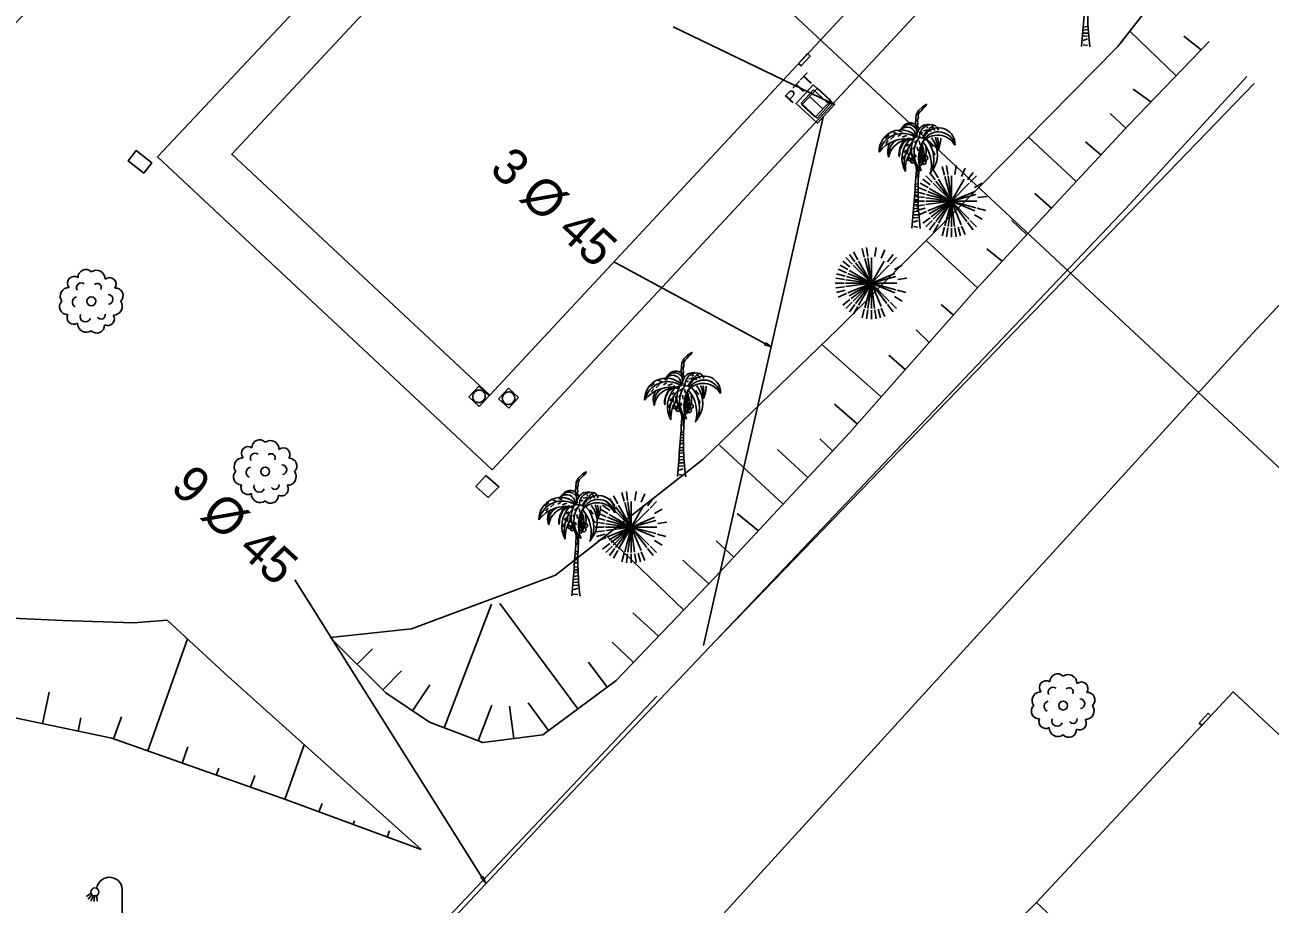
# Model space of a CAD drawing. Extents: x 343997 to 344255, y 298512 to 298767.
# Drawn here: x 344085.39 to 344119.67, y 298730.51 to 298754.72 of the extents above; entities that cross this region are included whole.
import ezdxf

# ---------------------------------------------------------------- set-up
doc = ezdxf.new("R2010")
doc.units = 0
for name, color, linetype in [('Default', 7, 'Continuous'), ('DH_CADRE -CARTOUCHE', 7, 'Continuous'), ('DH_CADRE-CARTOUCHE', 7, 'Continuous'), ('DH_NORD', 7, 'Continuous'), ('DIR-Projet VRD1', 7, 'Continuous'), ('EL-coffret', 7, 'Continuous'), ('GO_DALLE', 7, 'Continuous'), ('O-Projet New VRD', 7, 'Continuous'), ('PC_REBAR', 7, 'Continuous'), ('PS_OBJECT', 7, 'Continuous'), ('PS_PLATE', 7, 'Continuous'), ('RES_EAU PLUVIALE', 7, 'Continuous'), ('RES_ELECTRICITE', 7, 'Continuous')]:
    doc.layers.add(name, color=color, linetype=linetype)

# ---------------------------------------------------------------- blocks, each defined once
blk = doc.blocks.new('CT2')
at = {"layer": 'Default'}
blk.add_lwpolyline([(0, 0), (0.1, 0), (0.1, 0.1), (0, 0.1)], close=True, dxfattribs=at)
blk.add_lwpolyline([(0.05, 0.1), (0.05, 0)], dxfattribs=at)
blk.add_text('PTT', height=0.06, dxfattribs=at).set_placement((-0.03, 0.1425))
blk = doc.blocks.new('REG_INC')
at = {"layer": 'Default'}
for p, q in [((0, 0.1), (0.1, 0.1)), ((0, 0), (0, 0.1)), ((0.1, 0.1), (0.1, 0)), ((0.1, 0), (0, 0))]:
    blk.add_line(p, q, dxfattribs=at)
for centre, start, end in [((0.05, 0.0498), 90.00577, 135.00577), ((0.05, 0.05), 45.00687, 90.00687), ((0.0498, 0.05), 135.00554, 180.00554), ((0.0501, 0.05), 180.00663, 225.00663), ((0.0499, 0.0498), 225.00686, 270.00686), ((0.0499, 0.05), 270.00577, 315.00577), ((0.0499, 0.0499), 0.00663, 45.00663), ((0.0501, 0.0499), 315.00554, 0.00554)]:
    blk.add_arc(centre, 0.044, start, end, dxfattribs=at)
blk = doc.blocks.new('EDF1')
at = {"layer": 'Default'}
for points in [[(-0.0855, 0.1462), (-0.0985, 0.1373)], [(-0.083, 0.1422), (-0.0931, 0.1303)], [(-0.0793, 0.1397), (-0.086, 0.1257)], [(-0.0753, 0.1388), (-0.0781, 0.1235)], [(-0.0701, 0.14), (-0.0684, 0.1241)], [(0, 0.01), (0, 0.15)]]:
    blk.add_lwpolyline(points, dxfattribs=at)
for centre, radius in [((-0.075, 0.15), 0.0112), ((0, 0), 0.01)]:
    blk.add_circle(centre, radius, dxfattribs=at)
blk.add_arc((-0.035, 0.155), 0.0354, 351.8699, 171.8699, dxfattribs=at)
blk = doc.blocks.new('COCO')
at = {"layer": 'Default'}
for p, q in [((-0.0037, 0.106), (0.0056, 0.1071)), ((0.0058, 0.114), (-0.003, 0.1162)), ((-0.0026, 0.1226), (0.0061, 0.1212)), ((-0.0046, 0.0891), (0.0052, 0.0927)), ((0.0054, 0.0998), (-0.0041, 0.0985)), ((-0.0068, 0.0371), (0.0045, 0.0374)), ((0.0045, 0.047), (-0.0065, 0.0453)), ((-0.0062, 0.0537), (0.0046, 0.0552)), ((0.0047, 0.0655), (-0.0058, 0.0642)), ((0.0046, 0.0033), (-0.0076, 0.0051)), ((-0.0073, 0.017), (0.0045, 0.0209)), ((0.0045, 0.0292), (-0.007, 0.0288))]:
    blk.add_line(p, q, dxfattribs=at)
for points in [[(0.0029, 0.2551), (-0.0016, 0.2896), (0.0002, 0.3125), (0.0059, 0.3241), (0.0173, 0.3348), (0.0189, 0.3356), (0.0282, 0.3415), (0.0266, 0.3373), (0.02, 0.3318), (0.0143, 0.3247), (0.0093, 0.32), (0.0081, 0.3165), (0.0057, 0.3133), (0.0057, 0.3099), (0.006, 0.3037), (0.0039, 0.2989), (0.0039, 0.2944), (0.0049, 0.2877), (0.0037, 0.2841), (0.0013, 0.2736)], [(0.0013, 0.2736), (0.0036, 0.2813), (0.0046, 0.2746)], [(0.0283, 0.2765), (0.0331, 0.2786)], [(-0.0746, 0.2559), (-0.0864, 0.2483)], [(-0.077, 0.2413), (-0.0836, 0.2333)], [(-0.0607, 0.2534), (-0.0704, 0.2443)], [(-0.0636, 0.2639), (-0.0541, 0.2608)], [(-0.0421, 0.258), (-0.0503, 0.2523)], [(-0.0487, 0.268), (-0.0386, 0.265)], [(-0.0183, 0.2493), (-0.0348, 0.2417), (-0.0401, 0.2307), (-0.0448, 0.2203), (-0.0471, 0.2086), (-0.0474, 0.2023), (-0.0466, 0.1973), (-0.0455, 0.2054), (-0.0451, 0.2146), (-0.0387, 0.2292), (-0.0351, 0.2354), (-0.0284, 0.2404), (-0.0233, 0.2445), (-0.0012, 0.2495)], [(-0.0256, 0.2553), (-0.0385, 0.2508)], [(0.0015, 0.2414), (-0.0056, 0.2352)], [(0.0081, 0.2404), (0.0106, 0.2299)], [(0.0133, 0.2608), (0.0185, 0.2634)], [(0.0196, 0.2687), (0.0323, 0.2715)], [(-0.0276, 0.2151), (-0.0329, 0.2086)], [(-0.0203, 0.2314), (-0.0274, 0.2258)], [(-0.023, 0.2152), (-0.0237, 0.2043)], [(-0.0161, 0.2218), (-0.0158, 0.2122)], [(-0.004, 0.2247), (-0.0081, 0.2179)], [(0.0022, 0.224), (0.0043, 0.213)], [(0.0385, 0.237), (0.0469, 0.2254)], [(0.0473, 0.2115), (0.0509, 0.2012)], [(-0.0321, 0.1997), (-0.0364, 0.19)], [(-0.0059, 0.2024), (-0.0083, 0.1998)], [(-0.0025, 0.2032), (0.0002, 0.1954)], [(-0.0055, 0.0716), (0.0048, 0.0717), (0.0049, 0.0787), (-0.0051, 0.0795)]]:
    blk.add_lwpolyline(points, dxfattribs=at)
for centre, radius in [((-0.0187, 0.1897), 0.00384), ((-0.0144, 0.1978), 0.00616), ((-0.0124, 0.1896), 0.00376), ((-0.011, 0.184), 0.00471), ((0.0134, 0.1862), 0.00549), ((0.0208, 0.1822), 0.00626), ((0.0254, 0.1938), 0.00628)]:
    blk.add_circle(centre, radius, dxfattribs=at)
for centre, radius, start, end in [((-0.0123, 0.259), 0.0323, 122.3475, 158.7636), ((-0.0199, 0.2618), 0.0238, 4.5218, 154.101), ((-0.0252, 0.2556), 0.0231, 4.2441, 134.2103), ((-0.016, 0.2647), 0.0255, 21.0861, 122.3475), ((0.0376, 0.2508), 0.0372, 113.7681, 175.3309), ((0.0376, 0.2508), 0.0372, 113.7681, 175.3309), ((0.0418, 0.2527), 0.0326, 97.1248, 183.9512), ((0.1025, 0.2053), 0.0958, 126.6858, 153.1664), ((0.0618, 0.2316), 0.0451, 356.1627, 159.0009), ((0.0344, 0.2407), 0.0451, 69.0817, 104.862), ((-0.0254, 0.228), 0.0869, 28.4725, 37.0965), ((0.0493, 0.2767), 0.00679, 35.3205, 126.6858), ((-0.0054, 0.2379), 0.0738, 25.8194, 35.3205), ((-0.0427, 0.2113), 0.0595, 43.6121, 181.4625), ((-0.0291, 0.1543), 0.0918, 76.7389, 142.8025), ((-0.038, 0.1964), 0.0648, 57.9192, 166.6201), ((-0.0196, 0.1874), 0.0565, 78.514, 171.3504), ((-0.032, 0.2055), 0.0433, 119.0834, 188.7621), ((0.0362, 0.1922), 0.0754, 136.7113, 208.8221), ((0.062, 0.2159), 0.0753, 153.0868, 230.1124), ((0.0659, 0.2068), 0.0718, 142.3554, 222.2794), ((-0.0007, 0.2465), 0.00563, 81.7475, 144.3035), ((-0.0189, 0.121), 0.1324, 71.3715, 81.7475), ((0.0294, 0.2595), 0.0256, 198.6765, 199.7627), ((0.0963, 0.1939), 0.09, 143.9866, 203.4288), ((0.059, 0.2015), 0.0548, 29.5654, 139.3517), ((-0.0341, 0.19), 0.0828, 46.9767, 50.1231), ((0.0609, 0.2187), 0.0468, 12.1077, 148.3146), ((-0.0157, 0.2027), 0.074, 51.2475, 54.5217), ((-0.0341, 0.19), 0.0828, 334.0687, 41.194), ((-0.1005, 0.1577), 0.1786, 37.5668, 40.5156), ((-0.0157, 0.2027), 0.074, 315.1472, 39.0239), ((-0.1704, 0.1849), 0.2327, 7.5978, 16.3666), ((-0.0254, 0.228), 0.0869, 350.8883, 14.7063), ((-0.0482, 0.2552), 0.1161, 339.3597, 356.5925), ((-0.03, 0.212), 0.0482, 151.1331, 199.5942), ((0.0551, 0.179), 0.0879, 137.733, 194.3716), ((0.0649, 0.1599), 0.0949, 145.5146, 182.4528), ((0.0544, 0.1816), 0.0474, 137.1953, 172.8987), ((0.0308, 0.2014), 0.0226, 121.4297, 182.29), ((2.7302, 0.0106), 2.7266, 175.4791, 176.5597), ((0.0311, 0.2152), 0.0219, 141.856, 191.5175), ((0.0242, 0.1964), 0.0147, 110.9727, 165.9756), ((0.0404, 0.1878), 0.0354, 125.0585, 146.3893), ((0.0398, 0.2098), 0.0301, 136.4569, 162.0685), ((0.0357, 0.2084), 0.0244, 133.1184, 172.7534), ((-0.0759, 0.1958), 0.0922, 344.8505, 15.8988), ((-0.0404, 0.2045), 0.0619, 329.4666, 26.6793), ((-0.0289, 0.211), 0.0564, 317.8279, 12.3386), ((-0.0543, 0.1744), 0.096, 344.8781, 41.1461), ((-8.5428, 0.7294), 8.5622, 355.11326, 356.26352), ((-0.0279, 0.1637), 0.0281, 2.1499, 36.6325), ((0.0372, 0.1847), 0.0277, 133.5956, 173.487), ((0.0808, 0.1542), 0.0777, 142.2358, 156.28), ((-0.0265, 0.1505), 0.0316, 339.9997, 25.7228), ((0.0199, 0.166), 0.0176, 166.9443, 185.5966)]:
    blk.add_arc(centre, radius, start, end, dxfattribs=at)
blk.add_ellipse((2.7425, 0.0272), major_axis=(-2.7371, 0.0966), ratio=0.529859, start_param=6.255729, end_param=6.369141, dxfattribs=at)
blk = doc.blocks.new('ARB1')
at = {"layer": 'Default'}
blk.add_circle((0, 0), 0.0122, dxfattribs=at)
for centre, radius, start, end in [((-0.0471, 0.0503), 0.0183, 53.9554, 222.2066), ((-0.0153, 0.0664), 0.0211, 43.6925, 183.5969), ((0.0139, 0.0613), 0.0241, 358.4583, 125.1928), ((-0.0613, 0.0139), 0.0241, 88.4583, 215.1928), ((-0.0276, 0.037), 0.0134, 52.4396, 209.5496), ((0.0164, 0.038), 0.0112, 330.5895, 133.7127), ((0.0501, 0.0468), 0.0183, 325.1444, 131.0175), ((0.0664, 0.0153), 0.0211, 313.6925, 93.5969), ((-0.0373, -0.0024), 0.0149, 103.7092, 242.3465), ((0.0458, 0.0052), 0.0137, 276.6214, 88.967), ((0.0613, -0.0139), 0.0241, 268.4583, 35.1928), ((-0.0664, -0.0153), 0.0211, 133.6925, 273.5969), ((-0.0478, -0.0443), 0.019, 155.2243, 300.9377), ((-0.0139, -0.0613), 0.0241, 178.4583, 305.1928), ((-0.0163, -0.042), 0.0148, 159.5371, 338.1663), ((0.0153, -0.0664), 0.0211, 223.6925, 3.5969), ((0.0271, -0.038), 0.0112, 210.5895, 13.7127), ((0.0448, -0.0483), 0.0188, 243.1323, 33.0297)]:
    blk.add_arc(centre, radius, start, end, dxfattribs=at)
blk = doc.blocks.new('ARB2')
at = {"layer": 'Default'}
for p, q in [((-0.0513, 0.0525), (-0.0688, 0.0702)), ((-0.0438, 0.0589), (-0.0588, 0.0786)), ((-0.0356, 0.0642), (-0.0481, 0.0858)), ((-0.0181, 0.0716), (-0.0244, 0.0956)), ((-0.0088, 0.0736), (-0.0119, 0.0983)), ((0.0106, 0.0736), (0.0144, 0.0983)), ((0.0287, 0.0684), (0.0388, 0.0914)), ((0.0456, 0.0589), (0.0612, 0.0786)), ((0.0531, 0.0525), (0.0706, 0.0702)), ((-0.0675, 0.0286), (-0.09, 0.0381)), ((-0.0631, 0.0373), (-0.0844, 0.0497)), ((-0.0575, 0.0453), (-0.0775, 0.0605)), ((0.065, 0.0373), (0.0862, 0.0497)), ((-0.0731, 0), (-0.0981, 0)), ((-0.0725, 0.01), (-0.0969, 0.0133)), ((-0.0706, 0.0195), (-0.0944, 0.0259)), ((0.0744, 0.01), (0.0987, 0.0133)), ((-0.0725, -0.01), (-0.0969, -0.0133)), ((-0.0706, -0.0195), (-0.0944, -0.0259)), ((-0.0675, -0.0287), (-0.09, -0.0383)), ((0.0725, -0.0195), (0.0963, -0.0259)), ((-0.0575, -0.0455), (-0.0775, -0.0605)), ((-0.0513, -0.0527), (-0.0688, -0.0702)), ((-0.0438, -0.0591), (-0.0588, -0.0787)), ((-0.0356, -0.0644), (-0.0481, -0.0859)), ((0.0456, -0.0591), (0.0612, -0.0787)), ((0.0531, -0.0527), (0.0706, -0.0702)), ((0.065, -0.0373), (0.0862, -0.0498)), ((-0.0181, -0.0717), (-0.0244, -0.0956)), ((-0.0088, -0.0737), (-0.0119, -0.0983)), ((0.0013, -0.0741), (0.0013, -0.0989)), ((0.0106, -0.0737), (0.0144, -0.0983)), ((0.02, -0.0717), (0.0263, -0.0956)), ((0.0287, -0.0686), (0.0388, -0.0916))]:
    blk.add_line(p, q, dxfattribs=at)
for points in [[(0.0013, 0.0008), (0.0013, 0), (-0.0081, 0.0695)], [(0.0362, 0.0608), (0.0013, 0), (0.0013, 0.0702)], [(-0.0688, 0.0091), (0.0013, 0), (-0.0338, 0.0608)], [(-0.0487, 0.0495), (0.0013, 0), (-0.0669, 0.0181)], [(-0.0419, 0.0556), (0.0013, 0), (-0.0638, 0.0269)], [(-0.0169, 0.0677), (0.0013, 0), (-0.06, 0.035)], [(0.0656, 0.0269), (0.0013, 0), (0.0506, 0.0495)], [(-0.0487, -0.0497), (0.0013, 0), (-0.0694, 0)], [(-0.0638, -0.0269), (0.0013, 0), (-0.0688, -0.0092)], [(-0.0169, -0.0678), (0.0013, 0), (-0.06, -0.0352)], [(-0.0544, -0.0428), (0.0013, 0), (-0.0338, -0.0608)], [(-0.0081, -0.0695), (0.0013, 0), (-0.0419, -0.0558)], [(0.0013, -0.0702), (0.0013, 0), (0, 0)], [(0.0688, 0.0181), (0.0013, 0), (0.0713, 0)], [(0.0438, -0.0558), (0.0013, 0), (0.0656, -0.0269)], [(0.0506, -0.0497), (0.0013, 0), (0.0688, -0.0181)], [(0.01, -0.0695), (0.0013, 0), (0.0281, -0.0648)], [(0.0019, 0), (0.0013, 0), (0.0013, -0.0009)]]:
    blk.add_lwpolyline(points, dxfattribs=at)

msp = doc.modelspace()

# ---------------------------------------------------------------- linework, layer by layer
at = {"layer": 'DH_CADRE -CARTOUCHE'}
for points in [[(344112.242, 298759.628), (344105.157, 298766.24), (344091.09, 298751.159), (344098.189, 298744.522)], [(343997.309, 298660.673), (344147.183, 298520.807), (344245.09, 298625.72), (344095.215, 298765.586)]]:
    msp.add_lwpolyline(points, close=True, dxfattribs=at)
at = {"layer": 'DH_CADRE-CARTOUCHE'}
for points in [[(344035.538, 298697.865), (344038.262, 298695.856), (344041.267, 298693.813), (344044.479, 298691.842), (344047.664, 298690.365), (344050.648, 298689.339), (344052.822, 298689.099), (344054.599, 298689.128), (344056.124, 298689.428), (344057.609, 298690.129), (344058.956, 298690.85), (344060.299, 298691.725), (344061.274, 298692.556), (344063.092, 298694.498), (344091.5, 298724.03), (344099.786, 298732.889), (344115.711, 298749.674), (344119.028, 298753.296)], [(344122.649, 298749.916), (344119.175, 298746.216), (344104.333, 298729.921), (344103.629, 298728.425), (344103.178, 298726.908), (344102.994, 298725.349), (344103.009, 298724.152), (344103.293, 298722.366), (344103.622, 298721.156), (344104.336, 298719.642), (344105.154, 298718.475), (344128.542, 298697.099), (344156.76, 298672.229), (344158.923, 298671.699), (344160.816, 298671.605), (344163.478, 298672.279), (344165.611, 298673.484), (344167.1, 298674.65), (344168.229, 298675.97), (344184.084, 298692.584)]]:
    msp.add_lwpolyline(points, dxfattribs=at)
at = {"layer": 'DIR-Projet VRD1'}
msp.add_line((344119.229, 298753.108), (344104.185, 298737.527), dxfattribs=at)
for points in [[(344107.364, 298752.182), (344104.076, 298737.628)], [(344102.789, 298736.23), (344059.183, 298690.031)]]:
    msp.add_lwpolyline(points, dxfattribs=at)
at = {"layer": 'EL-coffret'}
for points in [[(344106.94, 298753.931), (344107.013, 298753.863), (344106.763, 298753.592), (344106.69, 298753.659)], [(344117.964, 298735.764), (344118.037, 298735.697), (344117.787, 298735.426), (344117.714, 298735.493)]]:
    msp.add_lwpolyline(points, close=True, dxfattribs=at)
at = {"layer": 'GO_DALLE'}
for points in [[(344104.157, 298767.174), (344089.042, 298751.089), (344098.26, 298742.47), (344113.295, 298758.646)], [(344098.083, 298742.316), (344098.44, 298741.995), (344098.144, 298741.71), (344097.809, 298742.011)], [(344098.083, 298742.316), (344097.809, 298742.011)], [(344136.362, 298708.941), (344135.692, 298708.293), (344122.611, 298720.578), (344112.611, 298729.909), (344113.24, 298730.553)]]:
    msp.add_lwpolyline(points, dxfattribs=at)
msp.add_lwpolyline([(344088.667, 298750.641), (344088.238, 298750.974), (344088.459, 298751.259), (344088.886, 298750.924)], close=True, dxfattribs=at)
at = {"layer": 'O-Projet New VRD'}
for points in [[(344107.521, 298752.607), (344103.242, 298754.672)], [(344107.095, 298753.07), (344107.683, 298752.529), (344107.209, 298752.014), (344106.62, 298752.556), (344107.094, 298753.071)], [(344107.103, 298752.931), (344107.544, 298752.525), (344107.206, 298752.157), (344106.765, 298752.563), (344107.103, 298752.931)], [(344105.776, 298745.939), (344101.607, 298748.196)], [(344097.975, 298731.248), (344092.824, 298739.438)]]:
    msp.add_lwpolyline(points, dxfattribs=at)
for points in [[(344107.534, 298752.634), (344107.683, 298752.529), (344107.508, 298752.58)], [(344105.79, 298745.965), (344105.934, 298745.853), (344105.761, 298745.912)], [(344098, 298731.264), (344098.07, 298731.096), (344097.949, 298731.232)]]:
    msp.add_lwpolyline(points, close=True, dxfattribs=at)
at = {"layer": 'PC_REBAR'}
for p, q in [((344114.53, 298754.495), (344114.643, 298754.498)), ((344114.643, 298754.594), (344114.533, 298754.577)), ((344114.536, 298754.662), (344114.644, 298754.677)), ((344114.644, 298754.157), (344114.522, 298754.175)), ((344114.525, 298754.294), (344114.643, 298754.334)), ((344114.643, 298754.416), (344114.528, 298754.413))]:
    msp.add_line(p, q, dxfattribs=at)
msp.add_arc((344029.17, 298761.419), 85.622, 355.11326, 356.26352, dxfattribs=at)
msp.add_ellipse((344142.023, 298754.396), major_axis=(-27.371, 0.966), ratio=0.529859, start_param=6.255729, end_param=6.369141, dxfattribs=at)
at = {"layer": 'PS_OBJECT'}
for p, q in [((344117.082, 298753.319), (344115.811, 298754.548)), ((344117.777, 298754.039), (344117.294, 298754.407)), ((344116.388, 298752.6), (344115.902, 298752.955)), ((344115.695, 298751.878), (344115.266, 298752.284)), ((344114.335, 298750.411), (344113.022, 298751.628)), ((344115.015, 298751.144), (344114.585, 298751.504)), ((344113.655, 298749.677), (344113.19, 298750.082)), ((344112.975, 298748.944), (344112.549, 298749.341)), ((344111.615, 298747.477), (344110.204, 298748.785)), ((344112.295, 298748.21), (344111.874, 298748.553)), ((344110.952, 298746.728), (344110.62, 298747.021)), ((344110.289, 298745.978), (344109.93, 298746.325)), ((344108.964, 298744.479), (344107.335, 298745.919)), ((344109.627, 298745.229), (344109.173, 298745.63)), ((344108.302, 298743.73), (344107.681, 298744.279)), ((344106.266, 298741.525), (344104.515, 298743.151)), ((344107.627, 298742.991), (344107.272, 298743.321)), ((344106.947, 298742.258), (344106.115, 298743.03)), ((344105.586, 298740.792), (344105.002, 298741.261)), ((344103.53, 298738.607), (344101.409, 298740.64)), ((344104.905, 298740.059), (344104.42, 298740.51)), ((344104.222, 298739.329), (344103.508, 298739.978)), ((344096.937, 298735.361), (344098.238, 298738.767)), ((344100.614, 298735.885), (344098.467, 298738.79)), ((344102.838, 298737.884), (344102.129, 298738.53)), ((344088.776, 298734.725), (344089.867, 298737.81)), ((344093.827, 298737.818), (344093.865, 298737.856)), ((344102.145, 298737.162), (344101.557, 298737.726)), ((344094.537, 298737.113), (344094.96, 298737.54)), ((344101.418, 298736.48), (344100.909, 298737.169)), ((344095.246, 298736.408), (344095.765, 298736.931)), ((344085.877, 298735.475), (344086.059, 298736.343)), ((344096.062, 298735.832), (344096.545, 298736.548)), ((344097.871, 298735.004), (344098.247, 298735.989)), ((344098.855, 298735.068), (344098.737, 298735.962)), ((344099.81, 298735.29), (344099.244, 298736.055)), ((344086.856, 298735.27), (344086.934, 298735.641)), ((344087.833, 298735.058), (344088.049, 298735.668)), ((344092.549, 298733.391), (344093.081, 298734.898)), ((344089.719, 298734.391), (344089.877, 298734.837)), ((344090.662, 298734.058), (344090.73, 298734.248)), ((344091.606, 298733.724), (344091.721, 298734.05)), ((344093.487, 298733.045), (344093.575, 298733.282)), ((344094.426, 298732.699), (344094.463, 298732.801)), ((344095.364, 298732.353), (344095.428, 298732.526))]:
    msp.add_line(p, q, dxfattribs=at)
for points in [[(344093.796, 298737.849), (344096.039, 298738.089), (344100.001, 298739.57), (344104.057, 298742.749), (344107.776, 298746.346), (344111.679, 298750.267), (344115.483, 298754.122), (344116.594, 298755.567)], [(344117.992, 298754.262), (344115.791, 298751.982), (344111.589, 298747.448), (344108.09, 298743.49), (344104.387, 298739.501), (344101.668, 298736.664), (344099.652, 298735.174), (344097.999, 298734.955), (344096.528, 298735.517), (344095.327, 298736.328), (344093.796, 298737.849)], [(344073.57, 298738.618), (344075.035, 298738.789), (344081.494, 298738.55), (344086.429, 298738.314), (344088.388, 298738.256), (344089.309, 298738.325), (344090.888, 298736.867), (344096.303, 298732.007)], [(344096.303, 298732.007), (344092.591, 298733.376), (344087.786, 298735.075), (344082.797, 298736.122), (344077.416, 298736.336), (344073.033, 298736.146), (344070.83, 298735.682)]]:
    msp.add_lwpolyline(points, dxfattribs=at)
at = {"layer": 'PS_PLATE'}
msp.add_lwpolyline([(344136.362, 298708.941), (344141.75, 298714.784), (344118.651, 298736.353), (344113.24, 298730.553)], close=True, dxfattribs=at)

# ---------------------------------------------------------------- block references
at = {"layer": 'DH_NORD', "xscale": 6.282348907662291, "yscale": 5.00972463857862, "rotation": 46.81817999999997}
msp.add_blockref('CT2', (344107.146, 298752.177), dxfattribs=at)
at = {"layer": 'PC_REBAR', "xscale": 10, "yscale": 10}
for name, p in [('COCO', (344109.929, 298749.121)), ('ARB2', (344110.885, 298749.866)), ('ARB2', (344108.681, 298747.61)), ('ARB1', (344087.222, 298747.11)), ('COCO', (344103.473, 298742.285)), ('ARB1', (344092.008, 298742.421)), ('COCO', (344100.566, 298738.997)), ('ARB2', (344102.073, 298740.891)), ('ARB1', (344113.973, 298735.975))]:
    msp.add_blockref(name, p, dxfattribs=at)
at = {"layer": 'RES_EAU PLUVIALE', "xscale": 3.8270894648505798, "yscale": -3.98010434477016, "rotation": 137.40121296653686}
for p in [(344097.9, 298744.216), (344098.714, 298744.166)]:
    msp.add_blockref('REG_INC', p, dxfattribs=at)
at = {"layer": 'RES_ELECTRICITE', "xscale": 10, "yscale": 10}
msp.add_blockref('EDF1', (344088.071, 298729.343), dxfattribs=at)

# ---------------------------------------------------------------- texts
at = {"layer": 'O-Projet New VRD'}
for s, p in [('3 Ø 45', (344098.15, 298750.705)), ('9 Ø 45', (344089.367, 298741.946))]:
    msp.add_text(s, height=1.0003, rotation=317.3672, dxfattribs=at).set_placement(p)

doc.saveas('drawing.dxf')
